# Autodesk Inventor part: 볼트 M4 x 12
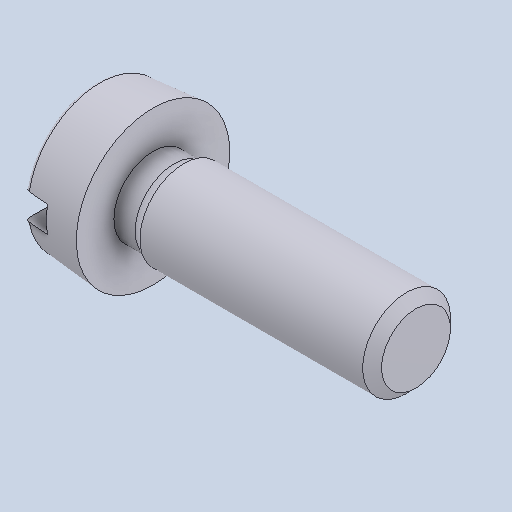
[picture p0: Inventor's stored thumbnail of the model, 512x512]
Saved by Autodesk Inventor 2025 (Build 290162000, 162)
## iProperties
Created: 2024-07
Part Number: 볼트 M4 x 12
Material: 강철, 연강
Description: 6각머리 태핑 나사
Document SubType Name: Modeling
Designer: anfro
Density: 7.85 g/cm^3
Appearance: 기본값
Author: jhkim
Sending System: Autodesk Inventor 2025
Preprocessor: ST-DEVELOPER v20
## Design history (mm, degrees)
feature "Solid1"
node "솔리드1"
